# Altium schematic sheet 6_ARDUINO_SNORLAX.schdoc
size 429 x 307 mm; Symbol: Drawing-Symbol_A4; Device: Drawing-Symbol_A4; @Project Name: Slowpoke; @Page Count: 7; @Update Date: 2025-12-15; @Create Date: 2025-12-13; @Schematic Name: Slowpoke_Sch; @Page No: 6; @Page Name: ARDUINO_SNORLAX; Company: Analog Devices, Inc.; Version: V1.0; Page Size: A4; @Create Time: 14:28:30; @Update Time: 16:08:31; Width: 1655; Height: 1170; Region Start: 1; X Region Count: 6; Y Region Count: 4; Blade Width: 10; Title Block Position: 3; @Board Name: Slowpoke
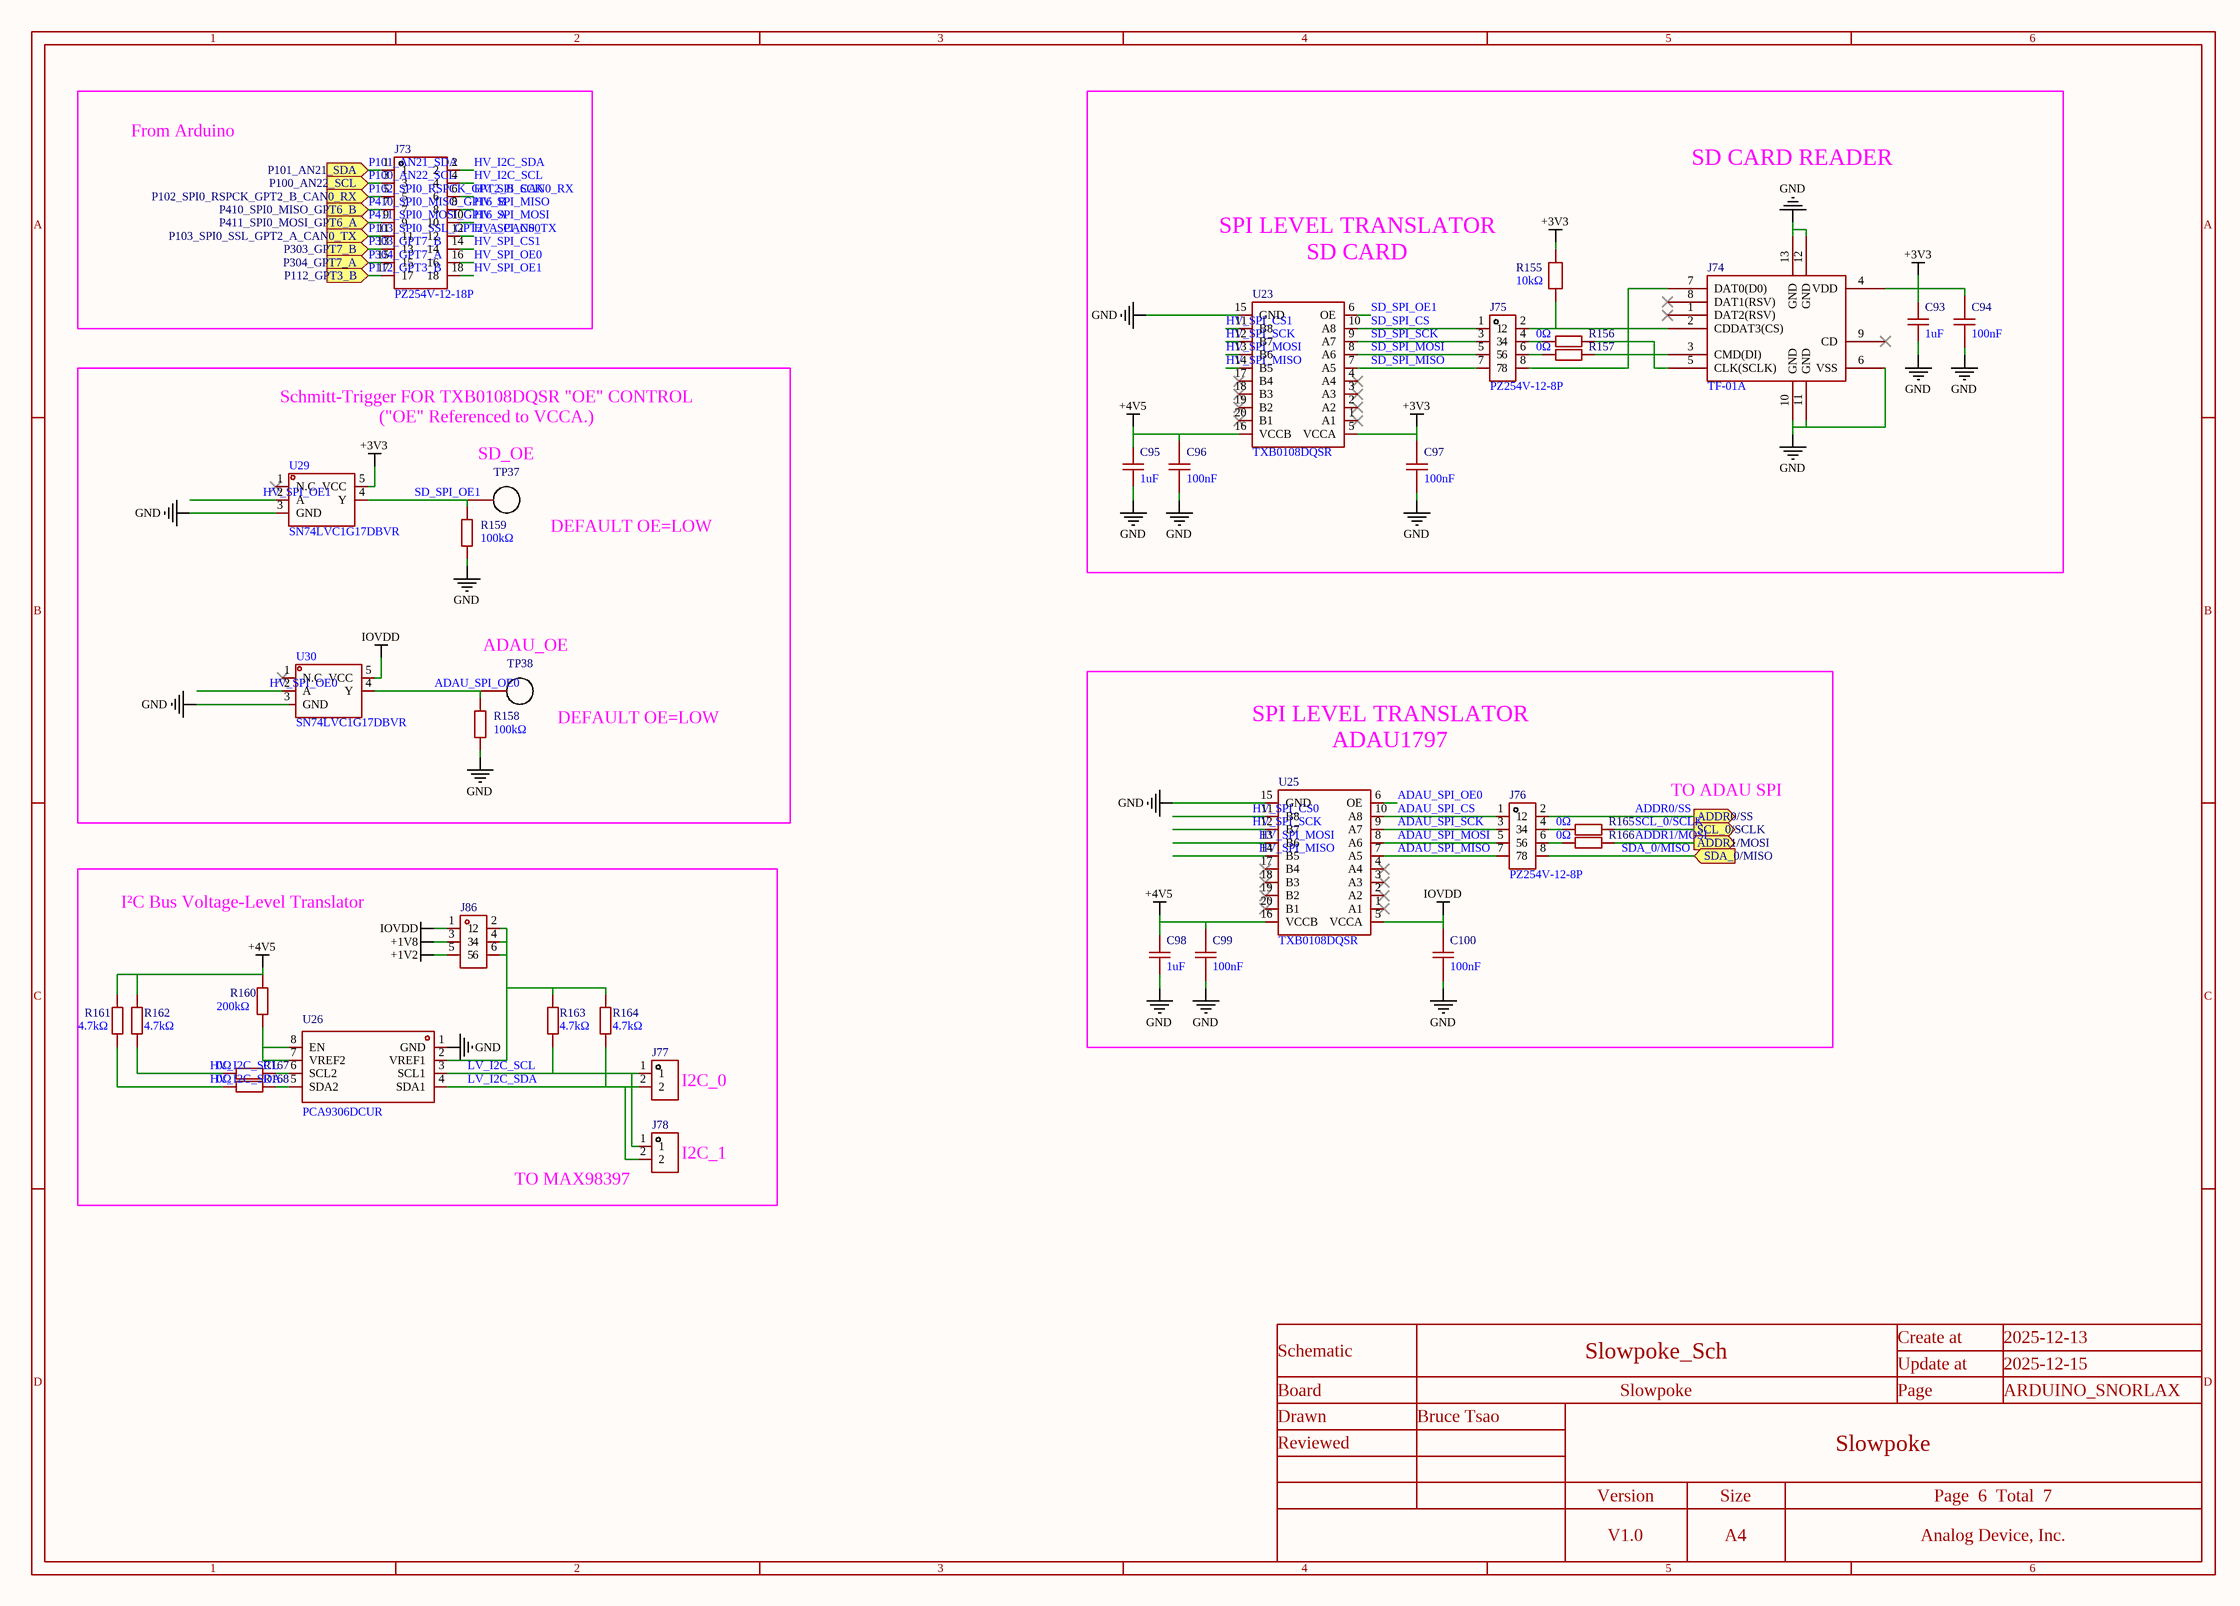
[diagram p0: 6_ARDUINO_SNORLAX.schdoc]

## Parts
C93  1uF  [C0402]
C94  100nF  [C0402]
C95  1uF  [C0402]
C96  100nF  [C0402]
C97  100nF  [C0402]
C98  1uF  [C0402]
C99  100nF  [C0402]
C100  100nF  [C0402]
J73  PZ254V-12-18P  [HDR-TH_18P-P2.54-V-M-R2-C9-S2.54]
J74  TF-01A  [TF-SMD_TF-01A]
J75  PZ254V-12-8P  [HDR-TH_8P-P2.54-V-M-R2-C4-S2.54]
J76  PZ254V-12-8P  [HDR-TH_8P-P2.54-V-M-R2-C4-S2.54]
J77  PZ254V-11-02P  [HDR-TH_2P-P2.54-V-M]  (value not drawn)
J78  PZ254V-11-02P  [HDR-TH_2P-P2.54-V-M]  (value not drawn)
J86  PZ254V-12-6P  [HDR-TH_6P-P2.54-V-M-R2-C3-S2.54]  (value not drawn)
R155  10kΩ  [R0402]
R156  0Ω  [R0402]
R157  0Ω  [R0402]
R158  100kΩ  [R0603]
R159  100kΩ  [R0603]
R160  200kΩ  [R0603]
R161  4.7kΩ  [R0603]
R162  4.7kΩ  [R0603]
R163  4.7kΩ  [R0603]
R164  4.7kΩ  [R0603]
R165  0Ω  [R0402]
R166  0Ω  [R0402]
R167  0Ω  [R0402]
R168  0Ω  [R0402]
TP37  RH-5002  [TESTPOINT-TH_BD2.5-D1.2_RH-5002]  (value not drawn)
TP38  RH-5002  [TESTPOINT-TH_BD2.5-D1.2_RH-5002]  (value not drawn)
U23  TXB0108DQSR  [SON-20_L4.0-W2.0-P0.40-BL]
U25  TXB0108DQSR  [SON-20_L4.0-W2.0-P0.40-BL]
U26  PCA9306DCUR  [SSOP-8_L2.0-W2.3-P0.50-LS3.1-BR]
U29  SN74LVC1G17DBVR  [SOT-23-5_L3.0-W1.7-P0.95-LS2.8-BR]
U30  SN74LVC1G17DBVR  [SOT-23-5_L3.0-W1.7-P0.95-LS2.8-BR]

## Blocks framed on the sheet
From Arduino: J73
SD CARD READER: C93-C97 J74 J75 R155-R157 U23
TO ADAU SPI: C98-C100 J76 R165 R166 U25

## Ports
ADDR0/SS (out), ADDR1/MOSI (out), P100_AN22_SCL (in), P101_AN21_SDA (in), P102_SPI0_RSPCK_GPT2_B_CAN0_RX (in), P103_SPI0_SSL_GPT2_A_CAN0_TX (in), P112_GPT3_B (in), P303_GPT7_B (in), P304_GPT7_A (in), P410_SPI0_MISO_GPT6_B (in), P411_SPI0_MOSI_GPT6_A (in), SCL_0/SCLK (out), SDA_0/MISO (in)

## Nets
+1V2: J86.5
+1V8: J86.3
+3V3: C93.2 C94.2 C97.2 J74.4(VDD) R155.2 U23.5(VCCA) U29.5(VCC)
+4V5: C95.2 C96.2 C98.2 C99.2 R160.2 R161.2 R162.2 U23.16(VCCB) U25.16(VCCB)
GND: C93.1 C94.1 C95.1 C96.1 C97.1 C98.1 C99.1 C100.1 J74.6(VSS) J74.10(GND) J74.11(GND) J74.12(GND) J74.13(GND) R158.1 R159.1 U23.15(GND) U25.15(GND) U26.1(GND) U29.3(GND) U30.3(GND)
IOVDD: C100.2 J86.1 U25.5(VCCA) U30.5(VCC)
ADAU_SPI_CS: J76.1 U25.10(A8)
ADAU_SPI_MISO: J76.7 U25.7(A5)
ADAU_SPI_MOSI: J76.5 U25.8(A6)
ADAU_SPI_OE0: R158.2 TP38.1 U25.6(OE) U30.4(Y)
ADAU_SPI_SCK: J76.3 U25.9(A7)
ADDR0/SS: J76.2 ; port ADDR0/SS
ADDR1/MOSI: R166.2 ; port ADDR1/MOSI
HV_I2C_SCL: J73.4 R162.1 R167.1
HV_I2C_SDA: J73.2 R161.1 R168.1
HV_SPI_CS0: J73.12 U25.11(B8)
HV_SPI_CS1: J73.14 U23.11(B8)
HV_SPI_MISO: J73.8 U23.14(B5) U25.14(B5)
HV_SPI_MOSI: J73.10 U23.13(B6) U25.13(B6)
HV_SPI_OE0: J73.16 U30.2(A)
HV_SPI_OE1: J73.18 U29.2(A)
HV_SPI_SCK: J73.6 U23.12(B7) U25.12(B7)
LV_I2C_SCL: J77.1 J78.1 R163.1 U26.3(SCL1)
LV_I2C_SDA: J77.2 J78.2 R164.1 U26.4(SDA1)
P100_AN22_SCL: J73.3 ; port P100_AN22_SCL
P101_AN21_SDA: J73.1 ; port P101_AN21_SDA
P102_SPI0_RSPCK_GPT2_B_CAN0_RX: J73.5 ; port P102_SPI0_RSPCK_GPT2_B_CAN0_RX
P103_SPI0_SSL_GPT2_A_CAN0_TX: J73.11 ; port P103_SPI0_SSL_GPT2_A_CAN0_TX
P112_GPT3_B: J73.17 ; port P112_GPT3_B
P303_GPT7_B: J73.13 ; port P303_GPT7_B
P304_GPT7_A: J73.15 ; port P304_GPT7_A
P410_SPI0_MISO_GPT6_B: J73.7 ; port P410_SPI0_MISO_GPT6_B
P411_SPI0_MOSI_GPT6_A: J73.9 ; port P411_SPI0_MOSI_GPT6_A
SCL_0/SCLK: R165.2 ; port SCL_0/SCLK
SD_SPI_CS: J75.1 U23.10(A8)
SD_SPI_MISO: J75.7 U23.7(A5)
SD_SPI_MOSI: J75.5 U23.8(A6)
SD_SPI_OE1: R159.2 TP37.1 U23.6(OE) U29.4(Y)
SD_SPI_SCK: J75.3 U23.9(A7)
SDA_0/MISO: J76.8 ; port SDA_0/MISO
NetJ74_2: J74.2(CDDAT3(CS)) J74.7(DAT0(D0)) J75.2 J75.8 R155.1
NetJ74_3: J74.3(CMD(DI)) R157.2
NetJ74_5: J74.5(CLK(SCLK)) R156.2
NetJ75_4: J75.4 R156.1
NetJ75_6: J75.6 R157.1
NetJ76_4: J76.4 R165.1
NetJ76_6: J76.6 R166.1
NetJ86_2: J86.2 J86.4 J86.6 R163.2 R164.2 U26.2(VREF1)
NetR160_1: R160.1 U26.7(VREF2) U26.8(EN)
NetR167_2: R167.2 U26.6(SCL2)
NetR168_2: R168.2 U26.5(SDA2)

Not connected (* = marked no-connect by the designer): J74 1(DAT2(RSV))* 8(DAT1(RSV))* 9(CD)*; U23 1(A1)* 2(A2)* 3(A3)* 4(A4)* 17(B4)* 18(B3)* 19(B2)* 20(B1)*; U25 1(A1)* 2(A2)* 3(A3)* 4(A4)* 17(B4)* 18(B3)* 19(B2)* 20(B1)*; U29 1(N.C)*; U30 1(N.C)*

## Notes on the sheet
- (near U23) SPI LEVEL TRANSLATOR
  SD CARD
- Schmitt-Trigger FOR TXB0108DQSR "OE" CONTROL
  ("OE" Referenced to VCCA.)
- (near TP37) SD_OE
- DEFAULT OE=LOW
- ADAU_OE
- (near U25) SPI LEVEL TRANSLATOR
  ADAU1797
- I²C Bus Voltage-Level Translator
- (near J77) I2C_0
- (near J78) I2C_1
- (near J78) TO MAX98397

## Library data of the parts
C93 C95 C98 = CL05A105KP5NNNC: Manufacturer: SAMSUNG(三星); Add into BOM: yes; Tolerance: ±10%; Voltage Rating: 10V; Temperature Coefficient: X5R
C94 C96 C97 C99 C100 = GRM155R61H104KE19D: Manufacturer: muRata(村田); Add into BOM: yes; Tolerance: ±10%
J73 = PZ254V-12-18P: Manufacturer: XFCN(兴飞); Add into BOM: yes; Pin Structure: 2x9P; Pitch: 2.54mm; Circluar Pins/Square Pins: Pin Header
J74 = TF-01A_C91145: Manufacturer: 韩国韩荣; Add into BOM: yes; Card Connection Mode: Push-Push; Card Type: MicroSD Card (TF Card); Connector Type: Connector and Ejector; Supplementary Features: With Locating Post
J75 J76 = PZ254V-12-8P: Manufacturer: XFCN(兴飞); Add into BOM: yes; Pin Structure: 2x4P; Pitch: 2.54mm; Circluar Pins/Square Pins: Pin Header
J77 J78 = PZ254V-11-02P: Manufacturer: XFCN(兴飞); Add into BOM: yes; Pin Structure: 1x2P; Pitch: 2.54mm; Circluar Pins/Square Pins: Pin Header
J86 = PZ254V-12-6P: Manufacturer: XFCN(兴飞); Add into BOM: yes; Pin Structure: 2x3P; Pitch: 2.54mm; Circluar Pins/Square Pins: Square Pins
R155 = HP02WAF1002TCE: Manufacturer: UNI-ROYAL(厚声); Add into BOM: yes; Tolerance: ±1%; Power(Watts): 100mW; Voltage-Supply(Max): 50V; Temperature Coefficient: ±100ppm/℃
R156 R157 R165-R168 = 0402WGJ0000TCE: Manufacturer: UNI-ROYAL(厚声); Add into BOM: yes; Tolerance: ±5%
R158 R159 = 0603WAF1003T5E: Manufacturer: UNI-ROYAL(厚声); Add into BOM: yes; Tolerance: ±1%; Power(Watts): 100mW; Voltage-Supply(Max): 75V; Temperature Coefficient: ±100ppm/℃
R160 = 0603WAF2003T5E: Manufacturer: UNI-ROYAL(厚声); Add into BOM: yes; Tolerance: ±1%; Temperature Coefficient: ±100ppm/℃
R161-R164 = 0603WAF4701T5E: Manufacturer: UNI-ROYAL(厚声); Add into BOM: yes; Tolerance: ±1%; Power(Watts): 100mW; Voltage-Supply(Max): 75V; Temperature Coefficient: ±100ppm/℃
TP37 TP38 = RH-5002: Manufacturer: 荣和; Add into BOM: yes; Connector Type: Pin Type (Through-Board); Plastic Color: White; Board Space (Diameter φ/ Length x Width): 2.5mm
U23 U25 = TXB0108DQSR: Manufacturer: TI(德州仪器); Add into BOM: yes
U26 = PCA9306DCUR: Manufacturer: TI(德州仪器); Add into BOM: yes; Channel Type: Bidirectional; Voltage - Supply(VCCA): 1.2V~3.3V; Voltage - Supply(VCCB): 1.8V~5.5V; Number of Circuits: 2; Output Type: Open Drain；Push-pull
U29 U30 = SN74LVC1G17DBVR: Manufacturer: TI(德州仪器); Add into BOM: yes; Input type: Schmitt Trigger; output type: Push-Pull; Voltage - Supply: 1.65V~5.5V; Number of Elements: 1; Current - Output Low(IOL): 32mA; Logic Family: 74LVC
